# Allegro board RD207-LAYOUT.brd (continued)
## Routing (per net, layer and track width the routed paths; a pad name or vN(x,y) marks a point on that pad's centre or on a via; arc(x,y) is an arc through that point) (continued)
N02981: length 223.9
  TOP w1: R3.1 28.84,273 ; R3.1 26.84,275 ; R3.1 25,273 ; R3.1 26.84,271 ; C10.2 27.25,224.5 ; C10.2 25,227 ; C10.2 27.25,229.5 ; C10.2 29.75,227 ; ZNR2.1 39.25,268.65 ; ZNR2.1 37.25,266.65 ; ZNR2.1 39.25,264.65 ; L1.5 103.72,230.18 ; L1.5 99.22,230.18 ; L1.5 101.47,227.93 ; R8.1 29.34,237 ; R8.1 31.34,235 ; R8.1 27.34,235 ; R8.1 29.34,233 ; ZNR3.1 39.75,244.65 ; ZNR3.1 41.75,246.65 ; ZNR3.1 41.75,242.65 ; F3.2 50.1,208 ; F3.2 52,209.9 ; F3.2 52,206.1 ; F3.2 53.9,208
  TOP w1.5: C3.2 34.75,293.75 ; C3.2 32,291 ; C3.2 34.75,288.25 ; C3.2 37.5,291 ; C15.1 29.05,294 ; C15.1 27,291.95 ; C15.1 24.95,294
  CONDUCTIVE2 w1: ZNR2.1 39.25,264.65 ; ZNR2.1 37.25,266.65 ; ZNR2.1 39.25,268.65 ; C15.1 27,292.3 ; C15.1 28.7,294 ; C15.1 25.3,294 ; R3.1 26.84,275 ; R3.1 28.84,273 ; R3.1 26.84,271 ; R3.1 24.84,273
  CONDUCTIVE2 w1.5: C3.2 32.7,291 ; C3.2 36.8,291 ; C3.2 34.75,288.95 ; C3.2 34.75,293.05
  CONDUCTIVE3 w1: F3.2 50.73,209.27 ; F3.2 53.27,206.73 ; F3.2 50.73,206.73 ; R8.1 31.34,235 ; R8.1 29.34,233 ; R8.1 27.34,235 ; R8.1 29.34,237 ; C10.2 29.05,227 ; C10.2 27.25,228.8 ; C10.2 25.45,227 ; C10.2 27.25,225.2 ; ZNR2.1 39.25,264.65 ; ZNR2.1 39.25,268.65 ; ZNR2.1 37.25,266.65 ; C15.1 27,292.3 ; C15.1 28.7,294 ; C15.1 25.3,294 ; C3.2 36.55,291 ; C3.2 32.95,291 ; C3.2 34.75,292.8 ; C3.2 34.75,289.2 ; ZNR3.1 39.95,244.65 ; ZNR3.1 41.75,242.85 ; ZNR3.1 41.75,246.45 ; R3.1 24.84,273 ; R3.1 28.84,273 ; R3.1 26.84,275 ; R3.1 26.84,271
  CONDUCTIVE3 w1.5: L1.5 99.07,230.18 ; L1.5 101.47,232.58 ; L1.5 103.87,230.18
  BOTTOM w1: F3.2 50.66,209.34 ; F3.2 50.66,206.66 ; F3.2 53.34,206.66 ; F3.2 53.34,209.34 ; R8.1 31.34,235 ; R8.1 27.34,235 ; R8.1 29.34,237 ; R8.1 29.34,233 ; ZNR2.1 39.25,264.65 ; ZNR2.1 39.25,268.65 ; ZNR2.1 37.25,266.65 ; ZNR3.1 41.75,246.65 ; ZNR3.1 41.75,242.65 ; ZNR3.1 39.75,244.65 ; C15.1 27,292.2 ; C15.1 25.2,294 ; C15.1 28.8,294 ; C10.2 27.25,229.5 ; C10.2 29.75,227 ; C10.2 27.25,224.5
  BOTTOM w1.5: C3.2 32,291 ; C3.2 34.75,293.75 ; C3.2 34.75,288.25 ; C3.2 37.5,291 ; R3.1 24.59,273 ; R3.1 29.09,273 ; R3.1 26.84,275.25 ; R3.1 26.84,270.75 ; L1.5 103.97,230.18 ; L1.5 98.97,230.18 ; L1.5 101.47,227.68
N16767228: length 187
  TOP w1: R7.2 111.84,283 ; R7.2 115.84,283 ; R7.2 113.84,281 ; R7.2 113.84,285 ; C17.1 100,299.2 ; C17.1 98.2,301 ; C17.1 101.8,301 ; C4.2 100.25,291 ; C4.2 105.25,291 ; C4.2 102.75,288.5 ; C4.2 102.75,293.5 ; R4.1 103.84,301 ; R4.1 101.84,299 ; R4.1 105.84,299 ; R4.1 103.84,297 ; C11.1 115.9,275 ; C11.1 113.75,277.5 ; C11.1 113.75,272.5 ; C11.1 111.25,275
  CONDUCTIVE2 w1: R7.2 113.84,281 ; R7.2 113.84,285 ; R7.2 116.1,283 ; R7.2 111.84,283 ; C17.1 101.7,301 ; C17.1 100,299.3 ; C17.1 98.3,301 ; C11.1 115.9,275 ; C11.1 111.95,275 ; C11.1 113.75,273.2 ; C11.1 113.75,276.8 ; C4.2 105.2,291 ; C4.2 102.75,292.8 ; C4.2 102.75,289.2 ; C4.2 100.95,291 ; R4.1 103.84,296.9 ; R4.1 101.84,299 ; R4.1 103.84,301 ; R4.1 105.84,299
  CONDUCTIVE2 w1.5: L1.4 86.33,222.83 ; L1.4 91.13,222.83 ; L1.4 88.73,225.23 ; L1.4 88.73,220.43 ; L2.3 163.75,223.8 ; L2.3 161.35,221.4 ; L2.3 161.35,226.2 ; L2.3 158.95,223.8
  CONDUCTIVE3 w1: C17.1 100,299.3 ; C17.1 101.7,301 ; C17.1 98.3,301 ; C11.1 111.95,275 ; C11.1 113.75,273.2 ; C11.1 113.75,276.8 ; C11.1 115.55,275 ; R4.1 103.84,297 ; R4.1 103.84,301 ; R4.1 105.84,299 ; R4.1 101.84,299 ; R7.2 115.84,283 ; R7.2 113.84,285 ; R7.2 113.84,281 ; R7.2 111.84,283 ; C4.2 102.75,292.8 ; C4.2 104.55,291 ; C4.2 100.95,291 ; C4.2 102.75,289.2
  BOTTOM w1: C4.2 102.75,293.5 ; C4.2 100.25,291 ; C4.2 105.25,291 ; C4.2 102.75,288.5 ; 113.75,277.5 C11.1 111.25,275 ; R4.1 103.84,297 ; R4.1 105.84,299 ; R4.1 101.84,299 ; R4.1 103.84,301 ; R7.2 113.84,285 ; R7.2 111.84,283 ; R7.2 113.84,281 ; C17.1 98.2,301 ; C17.1 100,299.2 ; C17.1 101.8,301
  BOTTOM w1.5: L1.4 91.23,222.83 ; L1.4 88.73,220.33 ; L1.4 88.73,225.33 ; L1.4 86.23,222.83 ; 158.85,223.8 L2.3 ; L2.3 163.85,223.8 ; L2.3 161.35,221.3 ; L2.3 161.35,226.3
N16767258: length 247.1
  TOP w1: L1.1 90.98,265.17 ; L1.1 88.73,267.42 ; L1.1 86.48,265.17 ; C3.1 57.25,293.5 ; C3.1 57.25,288.5 ; C3.1 59.75,291 ; C3.1 54.75,291 ; R3.2 47.16,271 ; R3.2 47.16,275 ; R3.2 45.5,273 ; R3.2 49.16,273 ; ZNR1.2 65.25,282.65 ; ZNR1.2 67.25,280.65 ; ZNR1.2 67.25,284.65 ; R2.2 59.84,299 ; R2.2 57.84,297 ; R2.2 57.84,301 ; R2.2 55.84,299 ; F1.2 58.6,281 ; F1.2 62.4,281 ; F1.2 60.5,282.9 ; F1.2 60.5,279.1 ; C2.1 66.25,291 ; C2.1 61.25,291 ; C2.1 63.75,293.5 ; C2.1 63.75,288.5 ; ZNR2.2 45.25,263.35 ; ZNR2.2 46.75,265.35 ; ZNR2.2 48.75,263.35 ; ZNR2.2 46.75,261.35 ; 54.2,301 C13.1 57.8,301
  CONDUCTIVE2 w1: F1.2 62.3,281 ; F1.2 60.5,279.2 ; F1.2 58.7,281 ; F1.2 60.5,282.8 ; R3.2 49.16,273 ; R3.2 47.16,275 ; R3.2 45.4,273 ; R3.2 47.16,271 ; C2.1 63.75,292.8 ; C2.1 65.55,291 ; C2.1 63.75,289.2 ; C2.1 61.95,291 ; C13.1 54.3,301 ; C13.1 57.7,301 ; C13.1 56,299.8 ; R2.2 55.84,299 ; R2.2 57.84,297 ; R2.2 59.84,299 ; R2.2 57.84,301 ; 67.25,284.65 ZNR1.2 65.25,282.65 ; ZNR2.2 46.75,265.35 ; ZNR2.2 46.75,261.35 ; ZNR2.2 48.75,263.35 ; ZNR2.2 45.25,263.35 ; C3.1 57.25,292.8 ; C3.1 57.25,289.2 ; C3.1 55.45,291 ; C3.1 59.05,291
  CONDUCTIVE3 w1: R3.2 47.16,275 ; R3.2 49.16,273 ; R3.2 47.16,271 ; ZNR2.2 48.75,263.35 ; ZNR2.2 45.25,263.35 ; ZNR2.2 46.75,265.35 ; ZNR2.2 46.75,261.35 ; F1.2 60.5,282.8 ; F1.2 60.5,279.2 ; F1.2 62.3,281 ; F1.2 58.7,281 ; R2.2 57.84,297 ; R2.2 57.84,301 C13.1 54.3,301 ; R2.2 55.84,299 ; C3.1 59.05,291 ; C3.1 55.45,291 ; C3.1 57.25,289.2 ; C3.1 57.25,292.8 ; C2.1 63.75,289.2 ; C2.1 61.95,291 ; C2.1 65.55,291 ; C2.1 63.75,292.8 ; ZNR1.2 67.25,284.65 ; ZNR1.2 64.2,282.65 ; ZNR1.2 67.25,280.65
  CONDUCTIVE3 w1.5: R2.2 59.8,299 ; L1.1 91.13,265.17 ; L1.1 86.33,265.17 ; L1.1 88.73,267.57
  BOTTOM w1: C13.1 57.8,301 ; C13.1 54.2,301 ; C13.1 56,299.7 ; R2.2 57.84,301 ; R2.2 55.84,299 ; R2.2 59.84,299 ; R2.2 57.84,297 ; C3.1 57.25,288.5 ; C3.1 54.75,291 ; C3.1 59.75,291 ; C3.1 57.25,293.5 ; R3.2 47.16,275 ; R3.2 47.16,271 ; R3.2 49.16,273 ; F1.2 58.6,281 ; F1.2 60.5,282.9 ; F1.2 62.4,281 ; F1.2 60.5,279.1 ; ZNR1.2 65.25,282.65 ; ZNR1.2 67.25,284.65 ; ZNR1.2 67.25,280.65 ; C2.1 61.25,291 ; C2.1 66.25,291 ; C2.1 63.75,293.5 ; C2.1 63.75,288.5 ; ZNR2.2 46.75,261.65 ; ZNR2.2 48.75,263.35 ; ZNR2.2 46.75,265.35
  BOTTOM w1.5: L1.1 86.23,265.17 ; L1.1 88.73,267.67 ; L1.1 91.23,265.17
N16767515: length 100.8
  TOP w1: 67.25,118.75 RLY1.4 65.25,116.8 ; 146.65,221.55 L2.2 ; L2.2 144.4,223.8 ; L2.2 148.9,223.8 ; RLY1.5 61.75,116.8 ; RLY1.5 59.75,119 ; RLY1.5 57.75,116.8 ; R1.2 64.53,127 ; R1.2 62.75,124.5 ; R1.2 60.25,127 ; R1.2 62.75,129.5
  CONDUCTIVE2 w1: R1.2 60.25,127 ; R1.2 62.75,129.5 ; R1.2 62.75,124.5 ; R1.2 64.55,127 ; RLY1.5 61.75,116.8 ; RLY1.5 57.75,116.8 ; RLY1.5 59.75,118.75 ; 65.25,116.8 RLY1.4 67.25,118.75
  CONDUCTIVE2 w1.5: 144.25,223.8 L2.2 146.65,221.4
  CONDUCTIVE3 w1: RLY1.5 59.75,118.75 ; RLY1.5 61.75,116.8 ; RLY1.5 57.75,116.8 ; R1.2 62.75,124.5 ; R1.2 62.75,129.5 ; R1.2 64.57,127 ; R1.2 60.25,127 ; 65.25,116.8 RLY1.4 67.25,118.75
  CONDUCTIVE3 w1.5: 146.65,220.98 L2.2 149.86,223.8
  BOTTOM w1: RLY1.5 59.75,119 ; RLY1.5 61.75,116.8 ; RLY1.5 57.75,116.8 ; R1.2 64.52,127 ; R1.2 60.25,127 ; R1.2 62.75,129.5 ; R1.2 62.75,124.5 ; 67.25,119 RLY1.4 65.25,116.8
  BOTTOM w1.5: 146.65,221 L2.2 143.75,223.8
N16768979: length 182.8
  TOP w1: C4.1 125.25,293.5 ; C4.1 127.75,291 ; C4.1 125.25,288.5 ; C4.1 122.75,291 ; C16.1 128,299.2 ; C16.1 129.8,301 ; C16.1 126.2,301 ; R5.2 131.84,297 ; R5.2 133.84,299 ; R5.2 131.84,301 ; R5.2 129.84,299 ; C5.1 130.75,293.5 ; C5.1 133.25,291 ; C5.1 130.75,288.5 ; C5.1 128.25,291 ; R4.2 124.16,301 ; R4.2 126.16,299 ; R4.2 124.16,297 ; R4.2 122.16,299 ; 132.83,249.98 L2.1 130.58,247.73
  CONDUCTIVE2 w1: R4.2 124.16,297 ; R4.2 124.16,301 ; R4.2 122.16,299 ; R4.2 126.16,299 ; R5.2 129.84,299 ; R5.2 131.84,301 ; R5.2 133.84,299 ; R5.2 131.84,297 ; C4.1 127.05,291 ; C4.1 123.45,291 ; C4.1 125.25,289.2 ; C4.1 125.25,292.8 ; C5.1 130.75,289.2 ; C5.1 128.95,291 ; C5.1 132.55,291 ; C5.1 130.75,292.8 ; C16.1 126.3,301 ; C16.1 129.7,301 ; C16.1 128,299.3
  CONDUCTIVE3 w1: R4.2 124.16,296.9 ; R4.2 122.16,299 ; R4.2 124.16,301 ; R4.2 126.16,299 ; C5.1 130.75,289.6 ; C5.1 132.6,291 ; C5.1 128.95,291 ; C5.1 130.75,292.8 ; C4.1 125.25,289 ; C4.1 127.05,291 ; C4.1 123.45,291 ; C4.1 125.25,292.8 ; C16.1 129.8,301 ; C16.1 126.3,301 ; C16.1 128,299.3 ; R5.2 131.84,296.9 ; R5.2 129.84,299 ; R5.2 133.84,299 ; R5.2 131.84,301
  CONDUCTIVE3 w1.5: 62.23,251.35 L1.2 ; L1.2 64.8,248.28 ; L1.2 67.94,251.35 ; 130.43,247.73 L2.1 132.83,250.13
  BOTTOM w1: R5.2 133.84,299 ; R5.2 131.84,297 ; R5.2 129.84,299 ; R5.2 131.84,301 ; C5.1 130.75,293.5 ; C5.1 128.25,291 ; C5.1 132.1,291 133.7,292.6 ; R4.2 124.16,297 ; R4.2 124.16,301 ; R4.2 126.16,299 ; R4.2 122.5,299 ; C4.1 122.75,291 ; C4.1 125.25,293.5 ; C4.1 127.75,291 ; C16.1 128,299.2 ; C16.1 126.2,301 ; C16.1 129.8,301
  BOTTOM w1.5: 64.8,248.85 L1.2 ; L1.2 62.3,251.35 ; L1.2 64.8,253.85 ; L1.2 67.3,251.35 ; 132.83,250.23 L2.1 130.33,247.73
N16769631: length 232.8
  TOP w1: C11.2 138.75,275 ; C11.2 136.25,272.5 ; C11.2 136.25,277.5 ; C11.2 134,275 ; C18.1 157.8,301 ; C18.1 156,299.2 ; C18.1 154.2,301 ; 136.16,283 R7.1 134.16,281
  TOP w1.5: C5.2 153.25,288.25 ; C5.2 156,291 ; C5.2 150.5,291 ; C5.2 153.25,293.75 ; L2.5 165.32,260.47 ; L2.5 171,260.47 ; L2.5 167.82,262.97 ; L2.5 167.82,257.97 ; L1.6 103.97,257.82 ; L1.6 101.47,255.32 ; L1.6 98.97,257.82 ; L1.6 101.47,260.32 ; R5.1 152.16,301.25 ; R5.1 154.41,299 ; R5.1 149.91,299 ; R5.1 152.16,296.75
  TOP w4: 106,253 122,237 ; 127,237 143,237
  CONDUCTIVE2 w1: C11.2 136.25,273.2 ; C11.2 138.05,275 ; C11.2 136.25,276.8 ; C11.2 134.45,275 ; C18.1 156,299.3 ; C18.1 154.3,301 ; C18.1 157.7,301 ; C5.2 151.45,291 ; C5.2 153.25,292.8 ; C5.2 153.25,289.2 ; C5.2 155.05,291 ; R5.1 154.16,299 ; R5.1 152.16,297 ; R5.1 152.16,301 ; R5.1 150.16,299 ; 134.16,281 R7.1 136.16,283
  CONDUCTIVE2 w1.5: 170.22,260.47 L2.5 167.82,262.87
  CONDUCTIVE3 w1: C18.1 157.7,301 ; C18.1 156,299.3 ; C18.1 154.3,301 ; C11.2 136.25,276.8 ; C11.2 134.45,275 ; C11.2 136.25,273.2 ; C11.2 138.05,275 ; 134.16,281 R7.1 134.16,285
  CONDUCTIVE3 w1.5: R5.1 152.16,296.75 ; R5.1 149.91,299 ; R5.1 152.16,301.25 ; R5.1 154.41,299 ; C5.2 153.25,293.05 ; C5.2 153.25,288.95 ; C5.2 151.2,291 ; C5.2 155.3,291 ; 167.82,262.87 L2.5 170.22,260.47 ; R7.1 136.96,283
  BOTTOM w1: R7.1 134.16,281 ; R7.1 132.16,283 ; R7.1 136.16,283 ; C11.2 138.75,275 ; C11.2 136.25,277.5 ; C11.2 136.25,272.5 ; C11.2 133.75,275
  BOTTOM w1.5: C5.2 153.25,288.25 ; C5.2 153.25,293.75 ; C5.2 156,291 ; C5.2 150.5,291 ; L2.5 165.5,260.47 ; L2.5 167.82,262.97 ; L2.5 170.32,260.47 ; R5.1 152.16,301.25 ; R5.1 149.91,299 ; R5.1 152.16,296.75 ; R5.1 154.41,299 ; 98.97,257.82 L1.6 ; L1.6 101.47,260.32 ; L1.6 103.97,257.82 ; C18.1 153.95,301 ; C18.1 158.05,301 ; C18.1 156,298.95
N16957930: length 2.4
  TOP w0.5: 32.58,35.5 34.42,35.5
  TOP w0.8: R11.2 32.58,35.5 ; 34.42,35.5 LED1.A
N16958743: length 3.1
  TOP w0.3: 42.35,70 41.49,70 ; 41.3,71.05 41.3,70.19 ; 41.3,68.95 41.3,69.81
  TOP w0.8: 41.3,70.19 R12.1 ; R12.1 41.49,70 ; R12.1 41.3,69.81
N17056068: length 30.7
  TOP w0.5: L3.2 45,33.8 ; L3.2 46.5,32.62 ; L3.2 43.5,32.62
  TOP w1: 42.9,33.45 C22.1 v1(45,35.5)
  TOP w1.2: C119.1 53.35,33 ; C119.1 53.35,39 ; C119.1 50.1,36
  TOP w1.6: PS2.2 50.1,42.45
  BOTTOM w1.6: PS2.2 50.1,40.6 v1(45,35.5)
N17056085: length 2.4
  TOP w0.5: 60.58,62 62.42,62
  TOP w0.8: R13.2 60.58,62 ; 62.42,62 LED2.A
N17156262: length 3.8
  TOP w0.3: 24.3,70 25.51,70 ; 25.7,68.9 25.7,69.81 ; 25.7,71.3 25.7,70.19
  TOP w0.8: 25.51,70 R10.1 ; R10.1 25.7,70.19 ; R10.1 25.7,69.81
N17206598: length 1.7
  TOP w0.3: 92.49,135.25 93.76,135.25
  TOP w0.8: 93.76,135.25 R72.1 ; R75.2 92.49,135.25
N17206600: length 1.7
  TOP w0.3: R76.1 95.5,134.45 95.55,134.5 95.55,135.06
  TOP w0.8: 95.55,135.06 R72.2
N17206602: length 1.6
  TOP w0.3: 95.5,131.76 95.5,130.49
  TOP w0.8: 95.5,130.49 R73.1 ; R76.2 95.5,131.76
N17206604: length 1.7
  TOP w0.3: 95.5,128.51 95.5,128 95.55,127.95 95.55,127.02
  TOP w0.8: 95.5,128.51 R73.2 ; R78.1 95.55,127.02
N17206606: length 1.7
  TOP w0.3: 93.76,127 92.49,127
  TOP w0.8: 92.49,127 R77.1 ; R78.2 93.76,127
N17206608: length 12.1
  TOP w0.3: 90.19,120.75 90.19,121.59 90.49,121.89 90.49,122.7 ; 90.69,126.92 90.69,125.79 R80.2 ; 90.49,123.08 90.49,124.7 ; 92.69,119.53 92.69,122.19 91.99,122.89 90.68,122.89
  TOP w0.45: R79.1 92.69,119.53
  TOP w0.6: L10.1 90.19,120.75
  TOP w0.8: 90.49,122.7 C86.1 ; C86.1 90.68,122.89 ; C86.1 90.49,123.08 ; 90.69,127.09 90.69,126.92 ; 90.49,124.7 R80.2
N17206622: length 17.8
  TOP w0.3: 92.69,118.25 92.69,116.39 ; 92.69,116.39 91.99,115.69 90.79,115.69 90.19,116.29 90.19,117.08 ; 92.69,116.39 93.19,115.89 TP32.1
  TOP w0.45: R79.2 92.69,118.25
  TOP w0.5: 94.69,115.54 94.69,113.96 D17.A ; 95.3,113.15 94.82,113.15 93.77,112.1 93.77,109.3 IC8.2
  TOP w0.6: L10.4 90.19,117.08
  TOP w0.8: 95.3,113.15 D17.A
  TOP w1.7: 94.69,115.54 TP32.1
N17206634: length 6.2
  TOP w0.3: 92.75,90.01 92.75,89.5 92.55,89.3 R147.1 ; 92.55,87.19 92.55,88.31 ; C152.2 93.55,86 93.55,84.62
  TOP w0.5: 93.55,84.62 IC17.4
  TOP w0.8: C152.2 92.55,87.19 ; 92.55,88.31 R147.1 ; 92.75,90.01 R83.2
N17206741: length 6.1
  TOP w0.3: R81.1 94.77,92.32 94.77,97.45
  TOP w1.5: 94.77,97.45 IC8.7
N17206751: length 6.8
  TOP w0.3: 94.45,87.19 94.45,88.31 ; 94.45,86.81 94.45,85.3 95.3,84.45 95.7,84.45 ; 94.25,90.01 94.25,89.25 94.45,89.05 R146.2
  TOP w0.5: 95.7,84.45 IC17.3
  TOP w0.8: 94.25,90.01 R81.2 ; 94.45,86.81 C151.1 94.45,87.19 ; 94.45,88.31 R146.2
N17206765: length 11.7
  TOP w0.3: 90.5,112.99 90.5,113.69 88.5,115.69 ; 89.19,116.97 89.19,116.29 88.59,115.69 88.5,115.69 ; 88.5,115.69 87.59,115.69 86.69,116.59 86.69,118.25 ; 92.31,112.8 90.69,112.8
  TOP w0.45: R86.2 86.69,118.25
  TOP w0.6: 89.19,116.97 L10.3
  TOP w0.8: R82.1 92.31,112.8 ; 90.69,112.8 R84.1 90.5,112.99
N17206769: length 3
  TOP w0.5: R82.2 92.5,110.3 92.23,110.03 92.23,108.63
  TOP w1.5: 92.23,108.63 IC8.3
N17206771: length 6.1
  TOP w0.3: R83.1 92.23,92.32 92.23,97.45
  TOP w1.5: 92.23,97.45 IC8.6
N17207012: length 1.5
  TOP w0.4: R87.2 156.05,126.75 R88.1
N17207014: length 1.4
  TOP w0.4: 153.27,126 154.23,126
  TOP w0.8: R89.1 153.27,126 ; 154.23,126 R88.2
N17207016: length 1.4
  TOP w0.4: 150.27,126 151.23,126
  TOP w0.8: R90.1 150.27,126 ; 151.23,126 R89.2
N17207018: length 1.4
  TOP w0.4: 147.27,126 148.23,126
  TOP w0.8: 148.23,126 R90.2 ; R91.1 147.27,126
N17207020: length 1.4
  TOP w0.4: 144.27,126 145.23,126
  TOP w0.8: R92.1 144.27,126 ; 145.23,126 R91.2
N17207022: length 10.8
  TOP w0.3: 141.49,122.2 141.49,121.7 141.19,121.4 141.19,120.66 ; 143.69,119.53 143.69,121.4 142.7,122.39 141.68,122.39 ; 141.49,122.58 141.49,123.7
  TOP w0.4: 141.49,123.98 141.49,125.04 R92.2
  TOP w0.45: R93.1 143.69,119.53
  TOP w0.6: L11.1 141.19,120.66
  TOP w0.8: 141.49,123.98 R95.2 141.49,123.7 ; 141.49,122.2 C91.1 ; C91.1 141.68,122.39 ; C91.1 141.49,122.58
N17207036: length 20.5
  TOP w0.3: 143.69,118.25 143.69,116.89 ; 143.69,116.89 143.69,116.18 143.2,115.69 142.5,115.69 ; 143.69,116.89 144.89,116.89 146.5,118.5 146.5,120.02 ; 142.5,115.69 141.7,115.69 141.19,116.2 141.19,117.03 ; 142.5,115.69 142.5,113.34 ; IC9.2 140.87,109.2 140.87,112.4 141.62,113.15 142.31,113.15
  TOP w0.45: R93.2 143.69,118.25
  TOP w0.6: L11.4 141.19,117.03
  TOP w0.8: 142.31,113.15 D18.A 142.5,113.34
  TOP w1.7: 146.5,120.02 TP33.1
N17207148: length 6.4
  TOP w0.3: 141.77,97.45 141.77,93.82 R96.1
  TOP w1.5: 141.77,97.45 IC9.7
N17207158: length 6.9
  TOP w0.3: 139.95,86.81 139.95,86.12 140.57,85.5 141,85.5 141.45,85.05 141.45,84.55 ; 140,90.26 140,89.25 139.95,89.2 R148.2 ; 139.95,87.19 139.95,88.31
  TOP w0.5: IC19.3 141.45,84.55
  TOP w0.8: 140,90.26 R96.2 ; 139.95,87.19 C153.1 139.95,86.81 ; 139.95,88.31 R148.2
N17207166: length 11.6
  TOP w0.3: 139.23,115.7 139.23,113.1 ; 139.23,115.7 138.2,115.7 137.69,116.21 137.69,118.25 ; 139.23,115.7 139.69,115.7 140.19,116.2 140.19,117.03 ; 136.88,112.91 139.04,112.91
  TOP w0.45: 137.69,118.25 R101.2
  TOP w0.6: L11.3 140.19,117.03
  TOP w0.8: 139.23,113.1 R97.1 139.04,112.91 ; R99.1 136.88,112.91
N17207170: length 3
  TOP w0.5: 139.23,108.63 139.23,111.03
  TOP w0.8: 139.23,111.03 R97.2
  TOP w1.5: IC9.3 139.23,108.63
N17207172: length 6.2
  TOP w0.3: R98.1 139.23,93.28 139.23,97.45
  TOP w1.5: 139.23,97.45 IC9.6
N17209468: length 1.7
  TOP w0.3: 395.99,254 397.06,254 R105.2
  TOP w0.8: R102.1 395.99,254
N17209470: length 1.7
  TOP w0.3: R108.1 394.2,252.74 394.2,253.81
  TOP w0.8: 394.2,253.81 R102.2
N17209472: length 2.2
  TOP w0.3: 394.2,248.69 394.2,250.26 R108.2
  TOP w0.8: 394.2,248.69 R106.1
N17209474: length 1.4
  TOP w0.3: 397.01,248.5 395.99,248.5
  TOP w0.8: R109.1 397.01,248.5 ; 395.99,248.5 R106.2
N17209476: length 2.3
  TOP w0.3: 399,246.37 399,247.4 398.8,247.6 398.8,248.31
  TOP w0.8: R107.1 399,246.37 ; 398.8,248.31 R109.2
N17209478: length 12
  TOP w0.3: 398.3,240.81 398.3,240 398,239.7 398,238.87 ; R110.2 399,243.7 399,244.68 ; 398.49,241 399.9,241 400.5,240.4 400.5,237.64 ; 398.3,241.19 398.3,242.81
  TOP w0.45: R103.1 400.5,237.64
  TOP w0.6: L12.1 398,238.87
  TOP w0.8: 398.3,242.81 R110.2 ; 398.49,241 C104.1 ; C104.1 398.3,241.19 ; C104.1 398.3,240.81 ; R107.2 399,244.68
N17209492: length 15.8
  TOP w0.3: 399.31,232.65 398.35,232.65 398.1,232.4 398.1,229.17 398.77,228.5 IC12.2 ; 399.5,232.84 399.5,234.2 ; 399.5,234.2 398.3,234.2 398,234.5 398,235.07 ; 399.5,234.2 400.5,235.2 ; 400.5,236.36 400.5,235.2 ; 400.5,235.2 TP39.1
  TOP w0.45: R103.2 400.5,236.36
  TOP w0.6: 398,235.07 L12.4
  TOP w0.8: 399.31,232.65 D19.A 399.5,232.84
N17209611: length 3
  TOP w0.5: 398.77,216.37 398.77,213.97
  TOP w0.8: 398.77,213.97 R111.1
  TOP w1.5: IC12.7 398.77,216.37
N17209621: length 16.7
  TOP w0.3: R115.2 398.25,205.8 v1(397.25,205.75) ; 400.69,205.8 401.5,205.8 402,205.3 402,203.25 402.95,202.3 404.05,202.3 ; v1(397.25,208.5) 397.25,210.57 R111.2 ; 400.31,205.8 399.19,205.8
  TOP w0.5: IC22.3 404.05,202.3
  TOP w0.8: 400.31,205.8 C105.1 400.69,205.8 ; 399.19,205.8 R115.2
  BOTTOM w0.3: v1(397.25,208.5) v1(397.25,205.75)
N17209635: length 10.2
  TOP w0.3: 396.23,234.2 396.7,234.2 397,234.5 397,235.24 ; 396.23,234.2 396.23,232.1 ; 396.23,234.2 395.4,234.2 394.5,235.1 394.5,236.36 ; 393.88,231.91 396.04,231.91
  TOP w0.45: R116.2 394.5,236.36
  TOP w0.6: L12.3 397,235.24
  TOP w0.8: 396.04,231.91 R112.2 396.23,232.1 ; R114.1 393.88,231.91
N17209639: length 3
  TOP w0.3: 396.23,230.12 396.23,227.55
  TOP w0.8: R112.1 396.23,230.12
  TOP w1.5: 396.23,227.55 IC12.3
N17209641: length 3
  TOP w0.5: 396.23,216.37 396.23,213.97
  TOP w0.8: 396.23,213.97 R113.1
  TOP w1.5: IC12.6 396.23,216.37
N17209643: length 25.7
  TOP w0.3: 396.23,211.9 396.23,207.2 ; 396.23,207.2 398.81,207.2 ; 396.23,207.2 396.23,203.52 399.25,200.5 405.5,200.5 406.7,201.7 406.7,202.13 ; 400.31,207.2 399.19,207.2
  TOP w0.5: IC22.4 406.7,202.13
  TOP w0.8: R113.2 396.23,211.9 ; 399.19,207.2 R104.1 398.81,207.2 ; C102.2 400.31,207.2
N17209881: length 1.9
  TOP w0.3: 429,248.01 429,246.49
  TOP w0.8: 429,246.49 R118.1 ; R117.2 429,248.01
N17209883: length 1.8
  TOP w0.3: R118.2 428.3,244.7 428.1,244.5 427.49,244.5
  TOP w0.8: 427.49,244.5 R119.1
N17209885: length 1.4
  TOP w0.3: 425.51,244.5 424.49,244.5
  TOP w0.8: R119.2 425.51,244.5 ; 424.49,244.5 R120.1
N17209887: length 1.4
  TOP w0.3: 422.51,244.5 421.49,244.5
  TOP w0.8: R120.2 422.51,244.5 ; 421.49,244.5 R121.1
N17209889: length 1.4
  TOP w0.3: 419.51,244.5 418.49,244.5
  TOP w0.8: 418.49,244.5 R122.1 ; R121.2 419.51,244.5
N17209891: length 14.3
  TOP w0.3: 415.5,237.64 415.5,239.9 414.4,241 413.37,241 ; 413,238.81 413,239.6 413.3,239.9 413.3,240.81 ; 416.7,244.43 416.7,243.4 416.3,243 413.49,243 ; 413.3,241.19 413.3,242.81
  TOP w0.45: 415.5,237.64 R123.1
  TOP w0.6: L13.1 413,238.81
  TOP w0.8: C109.1 413.37,241 ; C109.1 413.3,241.19 ; C109.1 413.3,240.81 ; 413.3,242.81 R125.2 413.49,243 ; R122.2 416.7,244.43
N17209905: length 18.2
  TOP w0.3: 416,234.5 416.9,234.5 TP40.1 ; 416,234.5 415.5,234.5 ; 416,234.5 416,232.84 ; 415.5,234.5 415,234 413.4,234 413,234.4 413,235.19 ; 415.5,234.5 415.5,236.36 ; 415.81,232.65 414.92,232.65 414.67,232.4 414.67,229.2 415.27,228.6 IC13.2
  TOP w0.45: R123.2 415.5,236.36
  TOP w0.6: L13.4 413,235.19
  TOP w0.8: 415.81,232.65 D20.A 416,232.84
N17210016: length 2.9
  TOP w0.5: IC13.7 415.29,215.5 415.29,214.07
  TOP w0.8: R126.1 415.29,214.07
N17210026: length 17.2
  TOP w0.3: 418.05,201.55 416.56,201.55 415.5,202.61 415.5,205.5 415.2,205.8 414.52,205.8 ; 414.31,205.8 413.19,205.8 ; R128.2 412.25,211.7 v1(411.5,211) ; C108.2 412.25,205.8 v1(411.5,205.75)
  TOP w0.5: IC24.3 418.05,201.55
  TOP w0.8: 413.19,205.8 C108.2 ; 414.31,205.8 R124.1 414.52,205.8
  BOTTOM w0.3: v1(411.5,211) v1(411.5,205.75)
N17210034: length 11.1
  TOP w0.3: 412.54,231.91 410.38,231.91 ; 412,235.07 412,234.4 411.6,234 ; 411.6,234 410,234 409.5,234.5 409.5,236.36 ; 411.6,234 412.73,232.87 412.73,232.1
  TOP w0.45: R131.2 409.5,236.36
  TOP w0.6: L13.3 412,235.07
  TOP w0.8: 412.54,231.91 R127.2 412.73,232.1 ; 410.38,231.91 R129.1
N17210038: length 3
  TOP w0.3: 412.73,227.55 412.73,230.12
  TOP w0.8: 412.73,230.12 R127.1
  TOP w1.5: IC13.3 412.73,227.55
N17210040: length 2.9
  TOP w0.5: 412.75,214.04 412.75,215.25 IC13.6
  TOP w0.8: R128.1 412.75,214.04
N17225441: length 5
  TOP w0.5: 377.73,245.2 377,245.2 376.53,244.73 376.12,244.73 ; 378,244.93 378,243.07
  TOP w0.6: PC1.1 376.12,244.73
  TOP w0.8: 378,244.93 R35.1 377.73,245.2 ; 378,243.07 R33.2
N17225495: length 8.3
  TOP w0.6: 358.05,247 358.58,247 358.68,247.1 359.94,247.1 ; 360.23,247.1 361.33,246 PC1.5
  TOP w0.8: 358.05,247 R36.1 ; 360.33,247.1 R34.1 359.94,247.1
N17225499: length 2.4
  TOP w0.6: 358.3,249 359.08,249 359.18,248.9 360.06,248.9
  TOP w0.8: 358.3,249 D11.C ; 360.33,248.9 R34.2 360.06,248.9
N17225644: length 4.5
  TOP w0.5: 377.73,221.7 377.17,221.7 376.7,221.23 376.12,221.23 ; 378,221.43 378,220.07
  TOP w0.6: PC2.1 376.12,221.23
  TOP w0.8: 378,220.07 R38.2 ; 378,221.43 R40.1 377.73,221.7
N17225700: length 8.3
  TOP w0.6: 360.33,223.1 360.93,222.5 PC2.5 365.73,222.5 ; 359.94,223.1 358.68,223.1 358.58,223 358.05,223
  TOP w0.8: 360.33,223.1 R39.1 359.94,223.1 ; 358.05,223 R41.1
N17225704: length 2.4
  TOP w0.6: 358.3,225 359.08,225 359.18,224.9 360.06,224.9
  TOP w0.8: 358.3,225 D12.C ; 360.33,224.9 R39.2 360.06,224.9
N17225875: length 22.5
  TOP w0.5: 353.68,205 352.7,205 352.2,204.5 352.2,198.3 353.9,196.6 355.04,196.6 ; 353.7,205.28 353.7,207.7 354.1,208.09 354.43,208.09
  TOP w0.6: 354.43,208.09 IC4.8
  TOP w0.8: 353.68,205 C64.1 353.7,205.28
  TOP w1.2: PS3.7 361.01,196.6 C63.1 355.04,196.6
N17225891: length 10.7
  TOP w0.5: 354.43,209.37 353.94,209.37 353.5,209.8 352.77,209.8 ; 356.43,214 353.3,214 352.5,213.2 352.5,210.07
  TOP w0.6: IC4.7 354.43,209.37
  TOP w0.8: R44.2 356.43,214 ; 352.77,209.8 R45.2 352.5,210.07
N17225996: length 1.9
  TOP w0.5: 359.93,214 358.57,214
  TOP w0.8: R43.1 359.93,214 ; 358.57,214 R44.1
N17226910: length 6
  TOP w0.5: 379.5,163.43 379.5,162.07 ; PC3.1 378.13,163.23 378.6,163.7 379.23,163.7
  TOP w0.8: 379.23,163.7 R48.1 379.5,163.43 ; 379.5,162.07 R46.2
N17226964: length 8.3
  TOP w0.6: 359.94,165.1 358.68,165.1 358.58,165 358.05,165 ; 365.73,164.5 PC3.5 360.93,164.5 360.33,165.1
  TOP w0.8: 359.94,165.1 R47.1 360.33,165.1 ; 358.05,165 R49.1
N17226968: length 2.4
  TOP w0.6: 358.3,167 359.08,167 359.18,166.9 360.06,166.9
  TOP w0.8: 360.06,166.9 R47.2 360.33,166.9 ; 358.3,167 D13.C
N17227113: length 6
  TOP w0.5: 376.12,139.23 377.5,139.23 377.97,139.7 379.23,139.7 ; 379.5,138.07 379.5,139.43
  TOP w0.6: PC4.1 376.12,139.23
  TOP w0.8: 379.5,139.43 R53.1 379.23,139.7 ; R51.2 379.5,138.07
N17227169: length 8.3
  TOP w0.6: R52.1 360.93,140.5 PC4.5 365.73,140.5 ; 359.94,141.1 358.68,141.1 358.58,141 358.05,141
  TOP w0.8: 358.05,141 R54.1 ; R52.1 359.94,141.1
N17227173: length 2.4
  TOP w0.6: 358.3,143 359.08,143 359.18,142.9 360.06,142.9
  TOP w0.8: R52.2 360.06,142.9 ; 358.3,143 D14.C
N17227344: length 20.9
  TOP w0.5: 354.36,129.09 354,129.09 353.7,128.8 353.7,127.28 ; 355.35,117.1 354.1,117.1 353.7,117.5 353.7,126.72
  TOP w0.6: 354.36,129.09 IC5.8
  TOP w0.8: 353.7,126.72 C72.1 353.7,127.28
  TOP w1.2: PS4.7 360.66,117.1 C71.1 355.35,117.1
N17227360: length 8.7
  TOP w0.5: 352,130.57 352,132.8 R57.2 ; R58.2 353.1,130.37 354.17,130.37
  TOP w0.6: IC5.7 354.17,130.37
  TOP w0.8: 352,130.57 R58.2
N17227465: length 2.4
  TOP w0.5: 357.93,135 356.07,135
  TOP w0.8: 356.07,135 R57.1 ; R56.1 357.93,135
N17228579: length 6
  TOP w0.5: PC5.1 378.4,81.23 378.87,81.7 379.35,81.7 ; 379.5,81.42 379.5,80.08
  TOP w0.8: 379.5,81.42 R61.1 379.35,81.7 ; 379.5,80.08 R59.2
N17228633: length 8.3
  TOP w0.6: 359.94,83.1 358.68,83.1 358.58,83 358.05,83 ; 365.73,82.5 PC5.5 360.93,82.5 360.33,83.1
  TOP w0.8: 360.33,83.1 R60.1 359.94,83.1 ; 358.05,83 R62.1
N17228637: length 2.4
  TOP w0.6: 360.06,84.9 359.18,84.9 359.08,85 358.3,85
  TOP w0.8: 358.3,85 D15.C ; 360.33,84.9 R60.2 360.06,84.9
N17228782: length 6
  TOP w0.5: 379.5,57.42 379.5,56.08 ; R66.1 379.03,57.23 376.12,57.23
  TOP w0.6: PC6.1 376.12,57.23
  TOP w0.8: 379.5,56.08 R64.2 ; R66.1 379.5,57.42
N17228838: length 8.3
  TOP w0.6: 360.33,59.1 360.93,58.5 PC6.5 365.73,58.5 ; 358.05,59 358.58,59 358.68,59.1 359.94,59.1
  TOP w0.8: 359.94,59.1 R65.1 360.33,59.1 ; 358.05,59 R67.1
N17228842: length 2.4
  TOP w0.6: 360.06,60.9 359.18,60.9 359.08,61 358.3,61
  TOP w0.8: 358.3,61 D16.C ; 360.06,60.9 R65.2 360.33,60.9
N17229013: length 20.4
  TOP w0.5: 352.7,44.77 352.7,46.3 353.5,47.09 353.93,47.09 ; 352.7,44.23 352.7,37.3 353.4,36.6 354.35,36.6
  TOP w0.6: IC6.8 353.93,47.09
  TOP w0.8: 352.7,44.77 C80.1 352.7,44.23
  TOP w1.2: PS5.7 360.66,36.6 C79.1 354.35,36.6
N17229029: length 10.8
  TOP w0.5: 353.93,53 352.2,53 351,51.8 351,48.58 ; 351.27,48.3 352.87,48.3 352.94,48.37 353.79,48.37
  TOP w0.6: IC6.7 353.79,48.37
  TOP w0.8: 351,48.58 R71.2 351.27,48.3 ; R70.2 353.93,53
N17229134: length 2.4
  TOP w0.5: 356.07,53 357.93,53
  TOP w0.8: 357.93,53 R69.1 ; R70.1 356.07,53
N17284402: length 35.3
  TOP w1.5: L5.2 273.7,249.45 ; L5.2 273.7,254.55 ; L5.2 276.25,252 ; Q1.D 341.43,252 ; Q1.D 343.83,254 ; Q1.D 343.83,250 ; Q1.D 345.83,252 ; D4.3 287.77,244.15 ; D4.3 285.37,246.55 ; D4.3 290.17,246.55 ; D4.1 290.17,257.45 ; D4.1 287.77,259.85 ; D4.1 285.37,257.45
  TOP w2.3: 285.37,228 D7.2 290.17,228
N17284406: length 35.2
  TOP w1.5: Q5.D 343.83,86 ; Q5.D 345.83,88 ; Q5.D 341.43,88 ; Q5.D 343.83,90 ; L9.2 276.25,88 ; L9.2 273.7,90.55 ; L9.2 273.7,85.45 ; D6.3 290.17,82.55 ; D6.3 285.37,82.55 ; D6.3 287.77,80.15 ; D6.1 287.77,95.85 ; D6.1 290.17,93.45 ; D6.1 285.37,93.45
  TOP w2.3: 290.17,64 D8.2 285.37,64
N17284446: length 9.8
  CONDUCTIVE3 w1.5: L4.1 202.95,252 ; L4.1 200.5,254.45 ; L4.1 200.5,249.55 ; L4.1 198.05,252
  vias: v1(78.5,129.5) v1(78.5,127.5) v1(78.5,110.5) v1(79.5,128.5) v1(79.5,111.5) v1(79.5,109.5) v1(80.5,129.5) v1(80.5,127.5) v1(80.5,110.5) v1(81.5,128.5) v1(81.5,111.5) v1(81.5,109.5) v1(82.5,129.5) v1(82.5,127.5) v1(82.5,110.5) v1(83.5,128.5) v1(83.5,111.5) v1(83.5,109.5)
N17284454: length 10.4
  CONDUCTIVE3 w5: L5.1 L4.2
  BOTTOM w5: L5.1 L4.2
N17284506: length 3.5
  BOTTOM w1.5: 371.5,296.5 371.5,294.5
  BOTTOM w1.9: R14.1 371.5,296.5 ; 371.5,294.5 R15.2
N17284767: length 9.8
  CONDUCTIVE2 w1.5: L6.1 198.05,170 ; L6.1 200.5,172.45 ; L6.1 200.5,167.55 ; L6.1 202.95,170
  vias: v1(127.5,116.25) v1(127.5,114) v1(128.5,129.5) v1(128.5,126.5) v1(128.5,117.25) v1(128.5,115.25) v1(129.5,128) v1(129.5,116.25) v1(129.5,114) v1(130.5,129.5) v1(130.5,126.5) v1(130.5,117.25) v1(130.5,115.25) v1(131.5,128) v1(131.5,116.25) v1(132.5,129.5) v1(132.5,126.5) v1(133.5,128)
N17284778: length 10.4
  CONDUCTIVE3 w5: L7.1 L6.2
  BOTTOM w5: L7.1 L6.2
N17284780: length 35.3
  TOP w1.5: L7.2 273.7,172.55 ; L7.2 276.25,170 ; L7.2 273.7,167.45 ; Q3.D 345.83,170 ; Q3.D 341.43,170 ; Q3.D 343.83,168 ; Q3.D 343.83,172 ; D5.3 290.17,164.55 ; D5.3 287.77,162.15 ; D5.3 285.37,164.55 ; D5.1 285.37,175.45 ; D5.1 290.17,175.45 ; D5.1 287.77,177.85
  TOP w2.3: 285.37,146 D9.2 290.17,146
N17285020: length 2.5
  BOTTOM w1.5: 371.5,277.53 R16.1
  BOTTOM w1.9: R17.2 371.5,277.53
N17285107: length 32
  TOP w1: L8.1 200.5,85.5 ; L8.1 198,88 ; L8.1 200.5,90.5
  CONDUCTIVE2 w1: L8.1 199,89.5 ; L8.1 202,89.5 ; L8.1 202,86.5 ; L8.1 199,86.5
  CONDUCTIVE3 w1: L8.1 199,89.5 ; L8.1 199,86.5 ; L8.1 202,86.5 ; L8.1 202,89.5
  BOTTOM w1: L8.1 200.5,90.5 ; L8.1 200.5,85.5 ; L8.1 198,88
  vias: v1(184.5,111.5) v1(184.5,109.5) v1(185.5,110.5) v1(186.5,111.5) v1(186.5,109.5) v1(187.5,110.5) v1(188.5,111.5) v1(188.5,109.5) v1(189.5,110.5)
N17285115: length 10.4
  CONDUCTIVE3 w5: L9.1 L8.2
  BOTTOM w5: L9.1 L8.2
N17285579: length 6
  TOP w0.3: 107.05,75.37 107.05,75.75 106.05,76.75 104,76.75 103.5,76.25 TP12.1
  TOP w0.5: 107.05,75.37 IC1.1
N17285634: length 11
  TOP w0.3: 412.8,107.31 412.8,105.5 ; 412.8,105.5 412.8,103.69 ; 412.8,105.5 412.12,105.5
  TOP w0.45: C52.1 412.12,105.5
  TOP w0.5: 412.8,103.22 412.8,102.1 413,101.9 413,100.75 ; 413.07,103.5 414.93,103.5
  TOP w0.8: 414.93,103.5 R20.1 ; R24.2 413.07,103.5 ; R24.2 412.8,103.69 ; R24.2 412.8,103.22 ; R22.2 412.8,107.31
  TOP w1: CN8.1 413,100.75
N17285636: length 11.3
  TOP w0.3: 413.3,110.13 413.3,109.7 414,109 414,108 ; D10.C/A 414,108 ; 414,108 414,106.7 C53.1 ; 413.05,110.3 412,110.3 411.2,109.5 411.2,107.69
  TOP w0.5: 413.3,110.13 IC2.3 413.05,110.3
  TOP w0.8: 411.2,107.69 R22.1
N17427639: length 6.4
  TOP w0.3: 139.05,84.55 139.05,85.25 138.05,86.25 138.05,86.81 ; 138.05,87.19 138.05,88.31 ; 138.05,88.52 138.05,89.5 138,89.55 138,90.26
  TOP w0.5: IC19.4 139.05,84.55
  TOP w0.8: 138.05,88.52 R149.1 138.05,88.31 ; 138.05,87.19 C154.2 138.05,86.81 ; 138,90.26 R98.2
N17427765: length 10.5
  TOP w0.3: 136.2,84.45 137.55,84.45 138.5,83.5 139.55,83.5 140.5,82.55 141.2,82.55 ; 136.45,87.19 136.45,88.31 ; 136.45,86.81 136.45,85.75 135.95,85.25 135.95,84.62
  TOP w0.5: 136.2,84.45 IC18.3 135.95,84.62 ; 141.2,82.55 IC19.1
  TOP w0.8: 136.45,88.31 R149.2 ; 136.45,86.81 C154.1 136.45,87.19
N17430423: length 11.9
  TOP w0.3: 90.95,84.45 91.25,84.45 ; 90.95,84.45 90.95,84.75 ; 90.95,84.45 90.65,84.45 ; 91.25,84.45 90.95,84.75 ; 91.25,84.45 91.5,84.45 92.45,83.5 94.25,83.5 95.2,82.55 95.7,82.55 ; 90.95,84.75 90.95,86.81 ; 90.95,84.75 90.65,84.45 ; 90.65,84.45 89.95,84.45 ; 90.95,87.19 90.95,88.31
  TOP w0.5: IC16.3 89.95,84.45 ; IC17.1 95.7,82.55
  TOP w0.8: 90.95,87.19 C152.1 90.95,86.81 ; 90.95,88.31 R147.2
N17437974: length 10
  TOP w0.3: 400.31,208.8 399.19,208.8 ; 404.05,204.2 403.3,204.2 402.75,204.75 402.75,207.3 ; 402.75,207.3 401.25,208.8 400.69,208.8 ; 402.75,207.3 403.8,207.3
  TOP w0.5: IC21.3 403.8,207.3 ; IC22.1 404.05,204.2
  TOP w0.8: 399.19,208.8 R104.2 ; 400.31,208.8 C102.1 400.69,208.8
N17438762: length 11.8
  TOP w0.3: R130.1 415.2,208.8 416.25,207.75 416.25,206.55 ; 418.05,203.45 416.8,203.45 416.25,204 416.25,206.55 ; 414.31,208.8 413.19,208.8 ; 416.25,206.55 418.05,206.55
  TOP w0.5: IC23.3 418.05,206.55 ; IC24.1 418.05,203.45
  TOP w0.8: R130.1 414.31,208.8 ; 413.19,208.8 C110.2
N17438821: length 27.7
  TOP w0.3: 414.31,207.2 413.19,207.2 ; 410.5,207.2 410.5,203 413,200.5 420.25,200.5 420.7,200.95 IC24.4 ; 410.5,207.2 410.5,208.25 412.25,210 413.09,210 R126.2 ; 410.5,207.2 412.81,207.2
  TOP w0.8: 413.19,207.2 C110.1 412.81,207.2 ; R130.2 414.31,207.2
N17447576: length 418.1
  TOP w0.3: 78.23,64 75.75,64 ; 75.75,64 75.5,64.25 ; 75.75,64 75.5,64 ; 75.75,64 75.5,63.75 ; 75.5,64.25 75.5,65.01 ; 75.5,64.25 75.5,64 ; 75.5,64 75.5,63.75 ; 75.5,63.75 75.5,61.75 85.35,51.9 111.85,51.9 146.25,17.5 280,17.5 286,11.5 389.3,11.5 404,26.2 404,73.5 409.12,78.62 IC15.18
  TOP w0.8: R141.1 75.5,65.01
  TOP w1.7: TP51.1 78.23,64
N17447582: length 6.2
  TOP w0.3: R142.2 77.1,66.8 75.69,66.8
  TOP w0.5: 75.65,70.45 75.65,69.95 75.5,69.8 75.5,67.08
  TOP w0.8: 75.69,66.8 R141.2 75.5,67.08 ; 75.65,70.45 PC7.1
N17447588: length 5.5
  TOP w0.5: 65.08,73 65.63,73 67.9,70.73 68.88,70.73
  TOP w0.8: PC7.6 68.88,70.73 ; 65.08,73 R140.1
N17447631: length 4.3
  TOP w0.4: 68.27,75.2 67.01,75.2 Q7.G
  TOP w0.8: 68.27,75.2 R143.2 68.5,74.12 PC7.4
N17453034: length 6.3
  TOP w0.3: 80.01,84.5 78.75,84.5 78.7,84.45 76.94,84.45 ; 80.2,84.69 80.2,85.25 80.05,85.4 IC32.3 ; C46.1 80.2,83.58 R19.2
  TOP w0.8: 80.01,84.5 R19.2 80.2,84.69 ; 76.94,84.45 R18.2
N17453159: length 5.2
  TOP w0.3: IC34.1 127.05,87.08 C54.2 126.3,88.58 R28.1 126.25,90.25 R25.2
N17453191: length 5.6
  TOP w0.3: 127.2,83.52 127.2,84.48 127.05,84.63 IC34.3 126.1,85.1 126,85.2 124.94,85.2 ; 127.2,83.31 127.2,82.33 C57.1
  TOP w0.8: 127.2,83.31 R31.2 127.2,83.52 ; 124.94,85.2 R30.2
N17453904: length 4.9
  TOP w0.3: 182.75,88.01 182.75,87.25 182.8,87.2 R27.2 ; 182.8,86.31 182.8,85.58 C55.1 183.05,84.67 IC36.1
  TOP w0.8: 182.8,86.31 R27.2 ; 182.75,88.01 R26.1
N17453936: length 5.5
  TOP w0.3: C56.2 181.45,79.08 181.45,80.23 ; R29.1 181.45,81.05 181.25,81.25 181.25,82.01 ; 181.44,82.2 182.25,82.2 182.4,82.35 IC36.3
  TOP w0.8: 181.25,82.01 R32.2 181.44,82.2 ; R29.1 181.45,80.23
N17455071: length 5.1
  TOP w0.3: IC32.1 78.33,87.15 C47.2 78.3,87.83 78.3,88.56 ; R21.1 78.3,89.5 R23.2
  TOP w0.8: 78.3,88.56 R21.1
N17610632: length 6.2
  TOP w0.3: IC35.1 183.05,78.42 C56.1 183.05,79.08 183.05,80.23 ; IC36.4 184.6,82.35 183.05,80.8 R29.2
  TOP w0.8: R29.2 183.05,80.23
N17611902: length 6.1
  TOP w0.3: 128.8,83.69 128.8,84.3 128.95,84.45 IC34.4 ; 128.8,83.48 128.8,82.33 C57.2 ; IC33.1 127.75,80.15 128.47,80.88 128.47,81.84
  TOP w0.45: C57.2 128.47,81.84
  TOP w0.8: 128.8,83.69 R31.1 128.8,83.48
N17613182: length 5.2
  TOP w0.3: 81.8,84.69 81.8,85.25 81.95,85.4 IC32.4 ; IC31.1 80.4,81.65 81.47,82.72 81.47,83.14 ; R19.1 81.8,83.58 C46.2
  TOP w0.45: C46.2 81.47,83.14
  TOP w0.8: 81.8,84.69 R19.1

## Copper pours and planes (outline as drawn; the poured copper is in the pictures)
5V on TOP (solid shape): 428.66,216.05 429.18,215.79 429.59,214.97 429.5,214.39 428.92,214.3 428.1,214.71 427.84,215.23 428.24,215.65
5V on TOP: 57.25,32.25 57,32.32 56.82,32.5 56.75,32.75 56.75,33.75 56.79,33.86 56.9,33.9 57.95,33.9 58.52,34.13 58.75,34.7 58.75,37.3 58.52,37.87 57.95,38.1 57.25,38.1 57,38.17 56.82,38.35 56.75,38.6 56.75,44.8 56.82,45.05 57,45.23 57.25,45.3 58.95,45.3 59.06,45.26 59.1,45.15 59.1,44.5 59.48,43.58 60.4,43.2 61.35,43.2 61.46,43.16 61.5,43.05 61.5,32.75 61.43,32.5 61.25,32.32 61,32.25
5V on TOP: 79.11,97.45 79.41,97.75 79.7,97.45 79.79,97.24 80,97.15 80.05,97.14 80.09,97.13 80.12,97.14 80.17,97.15 80.27,97.17 80.36,97.22 80.38,97.23 80.41,97.25 80.45,97.25 80.6,97.25 80.71,97.21 80.75,97.1 80.75,96.9 80.71,96.79 80.6,96.75 80.45,96.75 80.42,96.75 80.39,96.76 80.36,96.78 80.27,96.83 80.17,96.85 80.12,96.86 80.09,96.87 80.05,96.86 80,96.85 79.79,96.76 79.7,96.55 79.41,96.25 79.11,96.55
5V on CONDUCTIVE3: outline of 258 points within 56.5,7.5 442.5,248.25 ; 393 cut-outs
24V on TOP (solid shape): 66.2,91.9 66.48,92.13 66.7,91.85 66.69,91.73 67.18,91.24 67.3,91.25 67.58,91.03 67.35,90.75 66.38,90.66 66.18,90.73 66.11,90.93
24V on TOP: outline of 153 points within 17.7,28.1 47,72.15 ; 1 cut-out
24V on BOTTOM: outline of 199 points within 23.65,22.1 381.4,203.9 ; 8 cut-outs
+5V_AC on TOP: 152.4,109.75 152.29,109.79 152.25,109.9 152.25,110.05 152.06,110.51 151.6,110.7 151.4,110.7 151.3,110.69 151.2,110.67 151.06,110.69 151,110.81 151,111.7 151.05,111.81 151.16,111.85 151.2,111.85 151.4,111.85 151.97,112.08 152.2,112.65 152.2,115.43 152.2,115.45 152.25,115.62 152.26,115.76 152.26,115.96 152.03,116.53 151.46,116.76 151.26,116.76 151.21,116.76 151.17,116.75 151.05,116.79 151,116.9 151,118.75 151.04,118.86 151.15,118.9 153.74,118.9 153.87,118.88 154.1,118.75 154.62,118.23 154.9,117.86 155.19,117.54 155.95,116.78 155.98,116.74 156,116.69 156,116.64 156,112.88 155.96,112.78 155.85,112.73 155.55,112.73 155.48,112.74 155.43,112.78 153.17,111.85 155.52,111.15 155.57,111.2 155.64,111.21 155.85,111.21 155.96,111.17 156,111.06 156,110.25 155.93,110 155.75,109.82 155.5,109.75
+5V_AC on BOTTOM: 98.05,113.6 98.18,113.52 98.17,113.37 99,111.8 99.83,113.37 99.82,113.52 99.95,113.6 102.88,113.6 102.98,113.56 104.81,109.93 108.5,108.5 132.5,108.5 134.93,109.13 136.75,110.86 136.88,110.94 137.01,110.85 138.41,110.45 138.73,111.87 138.72,112.02 138.86,112.1 141.5,112.1 146.5,117.1 146.61,117.18 146.86,117.25 149.25,117.25 150.08,117.7 150.18,118.78 150.31,118.85 155.54,118.85 155.67,118.83 155.9,118.7 157.98,116.62 158.01,116.58 158.02,116.53 158.09,116.04 158.19,115.55 158.2,115.51 158.2,107.25 158.13,107 157.95,106.82 157.88,106.8 157.81,106.81 156.77,107.19 155.69,107.42 155.63,107.45 155.58,107.5 154.47,108.13 153.35,107.5 153.3,107.45 153.24,107.42 152.1,107.17 151.01,106.76 150.98,106.75 150.95,106.75 89.5,106.75 89.11,106.83 88.79,107.04 88.57,107.38 88.5,107.75 88.5,110.1 88.56,110.23 88.7,110.25 90,111.2 88.7,112.15 88.56,112.17 88.5,112.3 88.5,112.6 88.58,112.99 88.79,113.31 89.13,113.53 89.5,113.6 ; 2 cut-outs
+5V_DC on TOP: 426.45,230 426.2,230.07 426.02,230.25 425.95,230.5 425.95,236 426.02,236.25 426.2,236.43 426.45,236.5 431.05,236.5 431.3,236.43 431.48,236.25 431.55,236 431.55,231.01 431.53,230.88 431.4,230.65 430.82,230.07 430.74,230.02 430.65,230 429.96,230 429.76,230.1 429.72,230.32 428.46,231.97 427.21,230.32 427.17,230.1 426.97,230
+10V_U on CONDUCTIVE3: 351,221.37 351.07,221.54 351.25,221.62 351.31,221.61 351.37,221.59 351.67,221.47 351.99,221.45 352.1,221.45 352.19,221.45 353.33,222.55 352.19,223.65 352.15,223.65 351.97,223.73 351.9,223.92 351.99,224.26 352.19,224.54 353.75,226.1 353.88,226.33 353.9,226.46 353.9,263.95 353.97,264.2 354.15,264.38 354.4,264.45 354.59,264.45 354.69,264.43 354.77,264.37 366.68,252.47 366.72,252.41 366.75,252.29 366.75,196.98 366.75,196.94 366.74,196.9 366.68,196.81 366.58,196.74 366.55,196.74 365.94,196 366.55,195.26 366.62,195.24 366.68,195.19 366.73,195.11 366.75,195.02 366.75,194.5 366.46,193.79 365.75,193.5 352,193.5 351.29,193.79 351,194.5 ; 7 cut-outs
+10V_V on CONDUCTIVE3: 351,139.62 351.16,139.85 351.43,139.79 353.2,140.02 352.43,141.63 352.24,141.8 352.3,142.05 353.83,143.58 353.96,143.81 353.98,143.94 353.98,165.24 353.98,171.01 353.98,183.25 354.05,183.5 354.23,183.68 354.48,183.75 365.75,183.75 366.14,183.67 366.46,183.46 366.68,183.12 366.75,182.75 366.75,117.98 366.75,117.94 366.74,117.9 366.68,117.81 366.58,117.74 366.55,117.74 365.94,117 366.55,116.26 366.62,116.24 366.68,116.19 366.73,116.11 366.75,116.02 366.75,114.8 366.68,114.55 366.5,114.37 366.25,114.3 352,114.3 351.29,114.59 351,115.3 351,126.6 351.01,126.66 351.03,126.71 351.17,126.84 351.36,126.82 351.42,126.78 351.47,126.72 352.6,127 351.47,127.28 351.42,127.22 351.36,127.18 351.17,127.16 351.03,127.29 351.01,127.34 351,127.4 ; 6 cut-outs
+10V_W on CONDUCTIVE3: 351.6,45.1 351.18,45.67 351.05,45.76 351,45.91 351,57.37 351.12,57.58 351.37,57.59 351.67,57.47 351.99,57.45 352.1,57.45 352.19,57.45 353.33,58.52 352.25,59.65 352.02,59.81 352.08,60.08 353.83,61.83 353.96,62.06 353.98,62.19 353.98,83.24 353.98,89.01 353.98,101.29 354,101.39 354.06,101.47 354.38,101.68 354.75,101.75 365.75,101.75 366.14,101.67 366.46,101.46 366.68,101.12 366.75,100.75 366.75,45.18 366.65,44.98 366.42,44.95 366.4,44.95 366.34,44.99 366.29,45.04 365.2,44.7 366.29,44.36 366.34,44.41 366.4,44.45 366.42,44.45 366.65,44.42 366.75,44.22 366.75,37.48 366.69,37.32 366.55,37.24 366.11,36.98 365.94,36.5 366.11,36.02 366.55,35.76 366.69,35.68 366.75,35.52 366.75,34.75 366.46,34.04 365.75,33.75 352,33.75 351.61,33.83 351.29,34.04 351.07,34.38 351,34.75 351,44.29 351.05,44.44 351.18,44.53 ; 5 cut-outs
GND on TOP: 108.05,71.55 107.8,71.6 107.73,71.6 107.69,71.61 107.42,71.69 107.3,71.7 106.8,71.7 106.73,71.7 106.66,71.69 106.52,71.76 106.57,71.91 106.61,71.95 106.66,71.99 107.18,72.51 107.22,72.54 107.27,72.55 107.3,72.55 107.43,72.56 107.73,72.65 108.77,72.65 108.81,72.64 109.08,72.56 109.2,72.55 109.7,72.55 110.04,72.63 110.31,72.86 110.41,72.92 110.51,72.87 110.79,72.63 111.15,72.55 111.35,72.55 111.83,72.71 112.12,73.13 112.24,73.22 112.36,73.12 112.41,72.98 112.49,72.85 112.51,72.74 112.43,72.65 112.05,72.36 111.9,71.9 111.9,71.85 111.89,71.8 111.86,71.76 111.55,71.47 111.52,71.44 111.48,71.41 111.43,71.4 111.07,71.4 111.02,71.41 110.78,71.56 110.55,71.6 110.13,71.6 110.09,71.61 109.82,71.69 109.7,71.7 109.2,71.7 109.02,71.68 108.7,71.51 108.56,71.33 108.46,71.27 108.36,71.31
GND on TOP: 399.57,201.15 399.52,201.16 399.48,201.19 396.94,203.73 396.91,203.77 396.9,203.82 396.9,204.62 396.94,204.71 397.02,204.75 397.98,204.75 398.07,204.71 398.1,204.62 398.1,204.4 398.1,204.3 398.1,204.1 398.1,204.06 398.1,204.01 398.37,203.5 398.9,203.3 400.62,203.3 401.01,203.22 401.32,203.01 402.46,201.87 402.49,201.83 402.5,201.78 402.5,201.28 402.46,201.19 402.38,201.15
GND on TOP: 124.15,79.5 124.15,84.22 124.22,84.34 124.36,84.36 124.5,84.31 124.65,84.3 124.94,84.3 125.19,84.33 125.41,84.43 125.57,84.53 125.61,84.54 125.65,84.55 125.71,84.55 125.75,84.55 125.94,84.47 126.1,84.45 126.32,84.45 126.4,84.43 126.46,84.36 126.48,84.32 126.5,84.29 126.52,84.2 126.49,84.11 126.35,83.87 126.3,83.6 126.3,83.31 126.33,83.06 126.43,82.84 126.53,82.68 126.54,82.64 126.55,82.6 126.55,82.33 126.6,82.08 126.74,81.86 126.78,81.83 126.8,81.8 126.82,81.76 127.04,81.39 127.45,81.25 127.57,81.25 127.71,81.16 127.67,80.99 127.54,80.85 127.47,80.82 127.4,80.81 127.34,80.82 127.28,80.83 126.83,80.83 126.26,80.52 126.2,79.88 126.22,79.83 126.2,79.77 126.18,79.7 126.16,79.62 126.11,79.53 126.01,79.5 124.85,79.5 124.61,79.45 124.4,79.32 124.23,79.29 124.15,79.44
GND on TOP: outline of 2144 points within 7.5,7.5 442.5,248.25 ; 16 cut-outs
GND on TOP: 413.32,201.15 413.27,201.16 413.23,201.19 411.19,203.23 411.16,203.27 411.15,203.32 411.15,204.62 411.19,204.71 411.27,204.75 411.98,204.75 412.07,204.71 412.1,204.62 412.1,204.4 412.1,204.3 412.1,204.1 412.1,204.06 412.1,204.01 412.37,203.5 412.9,203.3 413.1,203.3 413.16,203.3 413.25,203.31 414.25,203.31 414.34,203.3 414.4,203.3 414.6,203.3 414.71,203.29 414.76,203.28 414.82,203.23 414.85,203.16 414.85,202.61 414.9,202.37 415.04,202.15 415.46,201.73 415.49,201.69 415.5,201.64 415.5,201.3 415.49,201.25 415.46,201.21 415.44,201.19 415.4,201.16 415.35,201.15
GND on TOP: outline of 261 points within 95.42,72.69 125.22,99.2
GND on TOP: 88.48,78.31 88.25,78.35 87.99,78.35 87.96,78.35 87.94,78.36 87.68,78.44 87.55,78.45 87.05,78.45 86.92,78.44 86.8,78.41 86.66,78.36 86.64,78.35 86.61,78.35 86.42,78.35 86.36,78.36 86.31,78.39 86.29,78.42 86.24,78.51 86.27,78.61 86.31,78.66 86.5,79.31 86.23,79.94 86.22,80.12 86.4,80.18 86.57,80.12 86.76,80.1 88.65,80.1 89.22,80.33 89.45,80.9 89.45,81.1 89.41,81.34 89.3,81.56 89.29,81.72 89.43,81.8 89.45,81.8 89.95,81.8 90.08,81.81 90.2,81.84 90.34,81.89 90.36,81.9 90.39,81.9 90.64,81.9 90.69,81.89 90.73,81.87 90.82,81.78 90.84,81.74 90.85,81.69 90.85,78.75 90.86,78.65 90.88,78.55 90.86,78.41 90.74,78.35 90.39,78.35 90.36,78.35 90.34,78.36 90.08,78.44 89.95,78.45 89.45,78.45 89.14,78.38 88.89,78.2 88.79,78.15 88.68,78.19
GND on TOP: outline of 198 points within 78.87,81.67 91.25,99.25 ; 1 cut-out
GND on BOTTOM: outline of 218 points within 7.5,7.5 442.5,248.25 ; 54 cut-outs
GND on CONDUCTIVE2: outline of 166 points within 7.5,7.5 442.5,248.25 ; 117 cut-outs
GND_5VAC on CONDUCTIVE2: 134.53,107.07 134.55,107.17 134.6,107.25 137.32,109.97 137.32,111.4 137.34,111.49 137.4,111.57 139.3,113.47 139.35,113.56 139.35,113.61 139.35,114.5 139.36,114.53 139.38,114.82 139.39,115.1 139.39,116.57 139.41,116.67 139.46,116.75 141.91,119.2 141.92,119.2 142.08,119.31 142.27,119.35 151.49,119.35 151.51,119.35 155.65,119.35 155.74,119.33 155.82,119.28 158.05,117.05 158.16,116.88 158.2,116.69 158.2,107.75 158.05,107.23 157.66,106.86 157.56,106.83 157.45,106.85 156.58,107.14 155.68,107.33 155.57,107.36 155.5,107.45 154.47,108.04 153.43,107.45 153.36,107.36 153.25,107.33 152.25,107.11 151.28,106.77 151.23,106.75 151.18,106.75 138.87,106.75 138.84,106.75 138.63,106.79 138.45,106.8 134.78,106.8 134.6,106.87 134.53,107.05 ; 3 cut-outs
GND_5VAC on CONDUCTIVE2: 88.5,112.5 88.58,112.89 88.79,113.21 89.13,113.43 89.5,113.5 100.79,113.5 100.92,113.48 101.15,113.35 101.43,113.07 101.48,112.99 101.5,112.9 101.5,112.5 102.58,109.23 105.4,107.24 105.57,106.96 105.32,106.75 89.5,106.75 88.79,107.04 88.5,107.75 ; 1 cut-out
GND_5VAC on CONDUCTIVE3: 158.2,107.75 157.91,107.04 157.2,106.75 156.88,106.75 156.84,106.75 156.8,106.76 156.31,106.9 155.81,107 155.69,107.06 155.62,107.17 155.62,107.18 154.47,108.04 153.31,107.18 153.31,107.17 153.25,107.07 153.15,107.01 152.62,106.9 152.13,106.76 152.09,106.75 152.05,106.75 138.87,106.75 138.84,106.75 138.63,106.79 138.45,106.8 133.12,106.8 133.07,106.81 132.64,106.96 132.25,107 120.75,107 120.31,106.94 119.84,106.76 119.78,106.75 89.5,106.75 88.79,107.04 88.5,107.75 88.5,112.5 88.58,112.89 88.79,113.21 89.13,113.43 89.5,113.5 100.79,113.5 100.92,113.48 101.15,113.35 105.6,108.9 105.83,108.77 105.96,108.75 129.39,108.75 130.26,108.83 131.1,109.05 131.89,109.42 132.61,109.92 132.93,110.21 141.92,119.2 142.08,119.31 142.27,119.35 151.49,119.35 151.51,119.35 155.65,119.35 155.74,119.33 155.82,119.28 158.05,117.05 158.16,116.88 158.2,116.69 ; 4 cut-outs
GND_5VDC on TOP: 420,225.75 419.75,225.82 419.57,226 419.5,226.25 419.5,229.09 419.56,229.24 419.7,229.33 420.45,230.61 419.1,231.23 418.86,231.25 418.75,231.46 418.75,232.84 418.84,233.25 419.08,233.59 419.16,233.63 419.25,233.65 419.9,233.65 420.18,233.7 420.42,233.84 420.63,234.12 420.7,234.45 420.7,236.04 420.77,236.29 420.95,236.48 421.2,236.54 422.3,236.54 422.48,236.47 422.55,236.29 422.55,232.4 422.67,231.98 422.99,231.69 423.11,231.55 423.11,231.36 423.06,231.23 423.05,231.1 423.05,230.9 423.15,230.55 423.42,230.31 423.46,230.29 423.5,230.25 423.61,230.15 423.83,230.02 423.96,230 424.79,230 424.92,229.98 425.15,229.85 425.75,229.25 430,229.25 430.25,229.18 430.43,229 430.5,228.75 430.5,226.25 430.43,226 430.25,225.82 430,225.75 429.96,225.75 429.81,225.8 429.72,225.93 428.46,226.89 427.21,225.93 427.12,225.8 426.97,225.75
GND_5VDC on CONDUCTIVE2: 429.84,225.8 429.69,225.85 429.6,225.97 428.46,226.78 427.33,225.97 427.24,225.85 427.09,225.8 392.11,225.8 392.01,225.82 391.93,225.87 389.37,228.43 389.32,228.51 389.3,228.61 389.3,235.55 389.37,235.73 389.55,235.8 426.7,235.8 426.91,235.69 426.94,235.46 427.5,234.65 428.06,235.46 428.09,235.69 428.3,235.8 428.45,235.8 428.66,235.69 428.69,235.46 429.25,234.65 429.81,235.46 429.84,235.69 430.05,235.8 430.2,235.8 430.41,235.69 430.44,235.46 431,234.65 431.56,235.46 431.59,235.69 431.8,235.8 435.21,235.8 435.43,235.68 435.43,235.43 434.03,230.86 434.7,226.14 434.67,225.91 434.47,225.8 ; 3 cut-outs
GND_24V on TOP (solid shape): 373.77,196.45 374.31,196.53 374.9,196.41 375.09,195.83 374.9,194.91 374.31,194.44 373.72,194.92 373.53,195.83 373.52,195.9 373.51,195.96
GND_24V on TOP (solid shape): 373.77,117.45 374.31,117.53 374.9,117.41 375.09,116.83 374.9,115.92 374.31,115.44 373.72,115.92 373.53,116.83 373.52,116.9 373.51,116.96
GND_24V on TOP (solid shape): 373.77,36.95 374.31,37.03 374.9,36.91 375.09,36.33 374.9,35.41 374.31,34.94 373.72,35.42 373.53,36.33 373.52,36.4 373.51,36.46
GND_24V on TOP: outline of 298 points within 33.9,32.4 71.4,99.25 ; 3 cut-outs
GND_24V on CONDUCTIVE2: 7.5,49.09 7.55,49.24 7.69,49.33 16,60 7.69,70.67 7.55,70.76 7.5,70.91 7.5,99 7.57,99.18 7.75,99.25 71.15,99.25 71.33,99.18 71.4,99 71.4,69.35 71.33,69.17 71.15,69.1 55.7,69.1 55.67,69.1 54.78,68.85 54.4,68.02 54.4,28.35 54.33,28.17 54.15,28.1 7.75,28.1 7.57,28.17 7.5,28.35 ; 18 cut-outs
/MAINRLY_24V on TOP (solid shape): 60.3,91.85 60.52,92.13 60.8,91.9 60.89,90.93 60.82,90.73 60.62,90.66 59.65,90.75 59.49,90.84 59.42,91 59.5,91.19 59.7,91.25 59.82,91.24 60.31,91.73
/MAINRLY_24V on BOTTOM: outline of 101 points within 56.5,85.1 166.75,95.2 ; 1 cut-out
AC_L_IN_W on TOP: 173.25,118.35 172.15,117.9 171.7,116.8 171.7,115.7 171.52,115.55 171.3,115.5 167.7,115.5 167.48,115.55 167.3,115.7 167.3,116.8 165.75,118.35 164.2,116.8 164.2,115.7 164.02,115.55 163.8,115.5 163.5,115.5 163.25,115.57 163.07,115.75 163,116 163,129 163.08,129.39 163.29,129.71 163.63,129.93 164,130 173.5,130 173.89,129.92 174.21,129.71 174.43,129.37 174.5,129 174.5,118.75 174.45,118.53 174.3,118.35 ; 1 cut-out
AC_L_IN_W on BOTTOM: outline of 99 points within 135.5,115.5 181,263.5 ; 2 cut-outs
AC_L_IN_W on CONDUCTIVE2, CONDUCTIVE3: 171.8,116 171.65,115.65 171.3,115.5 167.7,115.5 167.35,115.65 167.2,116 167.2,116.8 165.75,118.25 164.3,116.8 164.3,116 164.15,115.65 163.8,115.5 163.5,115.5 163.25,115.57 163.07,115.75 163,116 163,129 163.08,129.39 163.29,129.71 163.63,129.93 164,130 173.5,130 173.89,129.92 174.21,129.71 174.43,129.37 174.5,129 174.5,118.75 174.43,118.5 174.25,118.32 174,118.25 173.25,118.25 172.22,117.83 171.8,116.8 ; 1 cut-out
AC_L_IN_W on CONDUCTIVE3: outline of 83 points within 7.7,133 149.01,264.5 ; 1 cut-out
AC_N_IN on TOP: outline of 96 points within 101.5,118.5 188.3,252.25 ; 1 cut-out
AC_N_IN on BOTTOM: 114.25,126 114.35,125.52 114.62,125.12 117.43,122.31 117.48,122.22 117.5,122.13 117.5,121.35 116.25,121.35 115.15,120.9 114.7,119.8 114.7,118.5 110.3,118.5 110.3,119.8 108.75,121.35 107.2,119.8 107.2,118.5 104.9,118.5 104.53,118.58 104.21,118.79 101.79,121.21 101.58,121.53 101.5,121.91 101.5,131.5 101.79,132.21 102.5,132.5 114,132.5 114.18,132.43 114.25,132.25 ; 1 cut-out
